// Mitsubishi GX Works2 project: 35.10个数据存入10个D   PLC: FX3U/FX3UC

PROGRAM MAIN
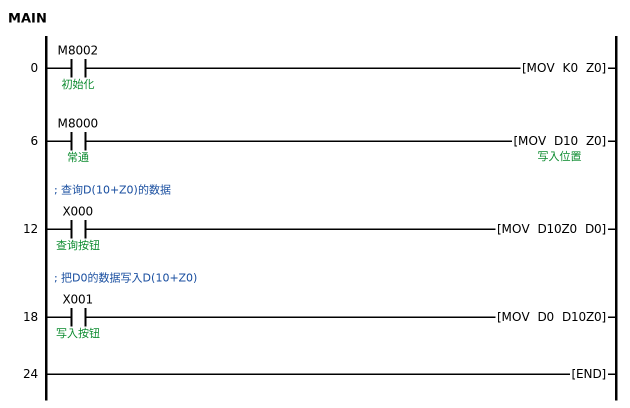
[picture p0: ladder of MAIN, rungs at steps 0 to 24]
0     LD      M8002  ; 初始化
      MOV     K0 Z0
6     LD      M8000  ; 常通
      MOV     D10 Z0  ; 写入位置
        [note] 把D10数据传到Z0
; 查询D(10+Z0)的数据
12    LD      X000  ; 查询按钮
      MOV     D10Z0 D0
        [note] 把D(10+Z0）传到D0
; 把D0的数据写入D(10+Z0)
18    LD      X001  ; 写入按钮
      MOV     D0 D10Z0
        [note] 把D0传到D(10+Z0)
24    END
END_PROGRAM

// device comments not shown above
X002  ; 启动按钮
